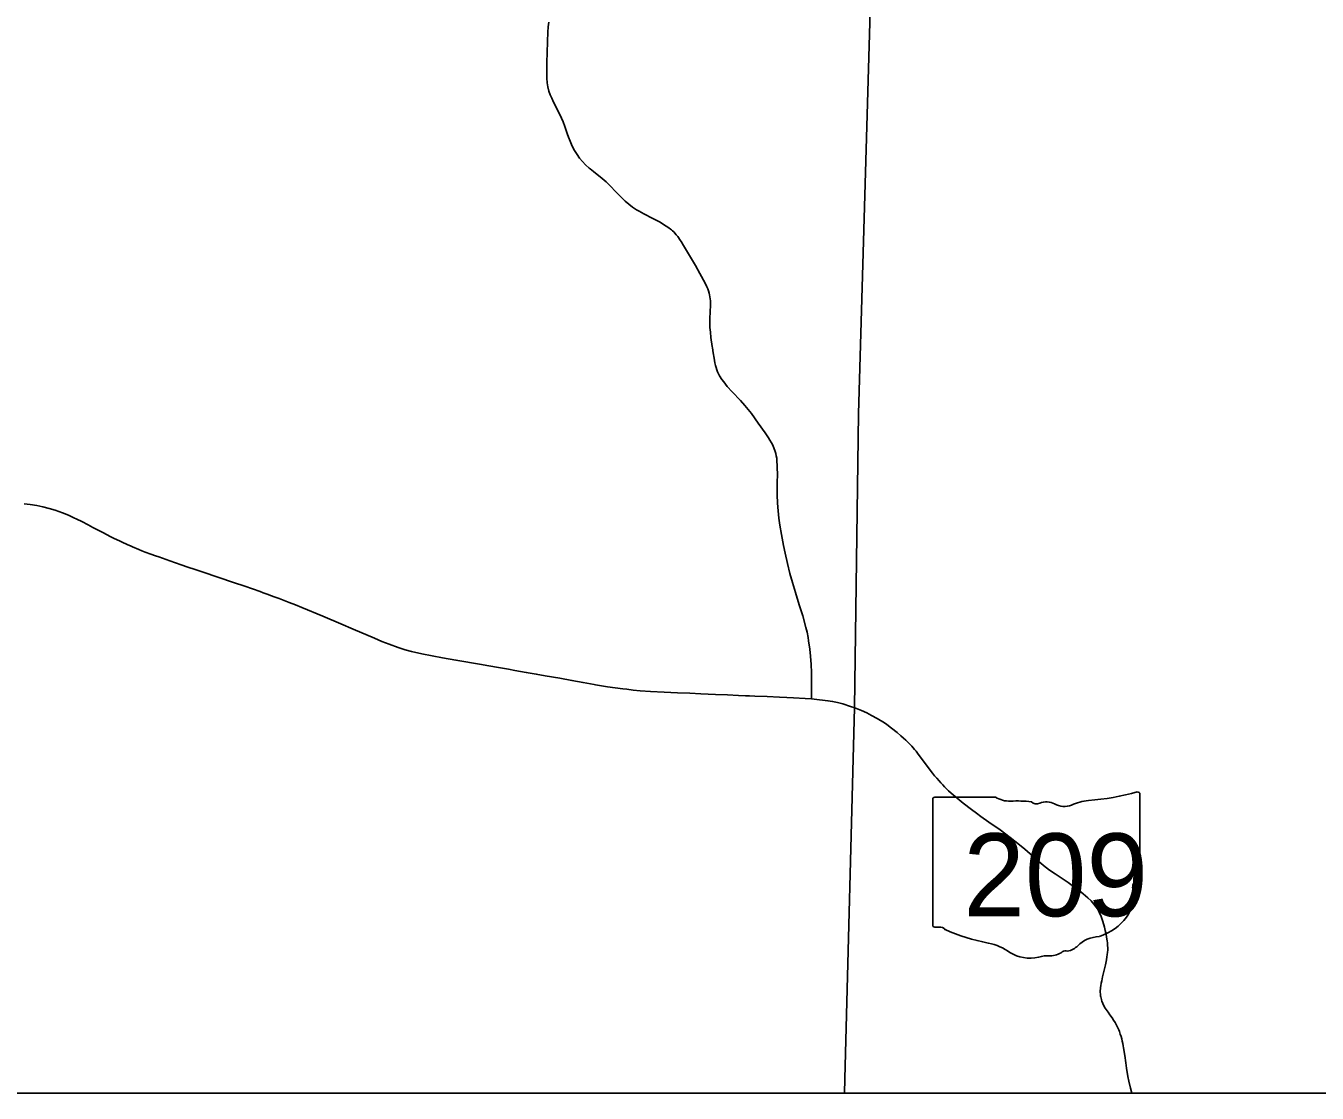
# Model space of a CAD drawing. Extents: x -12.1 to 34, y 0 to 22.
# Drawn here: x -10.219 to -8.292, y 10.977 to 12.57 of the extents above; entities that cross this region are included whole.
import ezdxf

# ---------------------------------------------------------------- set-up
doc = ezdxf.new("R2010")
doc.units = 0
for name, color, linetype in [('GM_X_State_Route', 7, 'Continuous'), ('GM_X_State_Shield', 7, 'Continuous'), ('GM_X_Township', 7, 'Continuous'), ('SH_Text', 7, 'Continuous')]:
    doc.layers.add(name, color=color, linetype=linetype)

msp = doc.modelspace()

# ---------------------------------------------------------------- linework, layer by layer
at = {"layer": 'GM_X_State_Route'}
for points in [[(-9.0469, 11.5656), (-9.0469, 11.569), (-9.0468, 11.5793), (-9.0467, 11.5896), (-9.0467, 11.5989), (-9.0468, 11.6051), (-9.0475, 11.6171), (-9.0483, 11.6292), (-9.0495, 11.6399), (-9.0512, 11.652), (-9.052, 11.6572), (-9.0536, 11.6651), (-9.0552, 11.6721), (-9.0599, 11.6893), (-9.0628, 11.6984), (-9.0653, 11.7059), (-9.0706, 11.7243), (-9.0754, 11.7394), (-9.079, 11.7528), (-9.0829, 11.7678), (-9.0864, 11.7829), (-9.0888, 11.7943), (-9.0918, 11.8109), (-9.0941, 11.8249), (-9.0956, 11.8353), (-9.0968, 11.8462), (-9.0975, 11.8574), (-9.098, 11.8699), (-9.098, 11.8897), (-9.0978, 11.8991), (-9.098, 11.9124), (-9.0985, 11.9218), (-9.0988, 11.9246), (-9.0994, 11.9284), (-9.1001, 11.9316), (-9.1006, 11.9333), (-9.1017, 11.9364), (-9.1041, 11.9424), (-9.1053, 11.9451), (-9.1067, 11.9478), (-9.109, 11.9517), (-9.1111, 11.9551), (-9.1162, 11.9627), (-9.1263, 11.9772), (-9.1365, 11.9912), (-9.1463, 12.0034), (-9.1528, 12.0107), (-9.1652, 12.0239), (-9.1725, 12.0317), (-9.1779, 12.0385), (-9.1808, 12.0422), (-9.184, 12.0475), (-9.187, 12.0537), (-9.1881, 12.0563), (-9.1893, 12.0598), (-9.1902, 12.0628), (-9.1911, 12.0669), (-9.1923, 12.074), (-9.1936, 12.0818), (-9.1947, 12.0892), (-9.195, 12.0915), (-9.1969, 12.105), (-9.1978, 12.1127), (-9.1985, 12.1197), (-9.1988, 12.1261), (-9.1986, 12.1336), (-9.1982, 12.1427), (-9.1977, 12.1535), (-9.1978, 12.1595), (-9.1981, 12.1626), (-9.1985, 12.1655), (-9.199, 12.1685), (-9.1996, 12.1711), (-9.2006, 12.1742), (-9.2018, 12.1774), (-9.2029, 12.1802), (-9.2054, 12.1856), (-9.2134, 12.2005), (-9.22, 12.2122), (-9.2287, 12.2269), (-9.2378, 12.2419), (-9.2414, 12.2478), (-9.2429, 12.25), (-9.2466, 12.2553), (-9.2487, 12.258), (-9.2524, 12.2625), (-9.2542, 12.264), (-9.2556, 12.2652), (-9.2571, 12.2665), (-9.2597, 12.2685), (-9.2636, 12.2711), (-9.2738, 12.2771), (-9.2835, 12.2824), (-9.297, 12.2893), (-9.3042, 12.2931), (-9.3081, 12.2954), (-9.3097, 12.2964), (-9.3139, 12.2993), (-9.3194, 12.3035), (-9.3251, 12.3084), (-9.3314, 12.3144), (-9.339, 12.3223), (-9.3474, 12.3312), (-9.3531, 12.3368), (-9.3592, 12.342), (-9.3722, 12.3524), (-9.3771, 12.3563), (-9.3787, 12.3576), (-9.3839, 12.3624), (-9.3888, 12.3672), (-9.3929, 12.3721), (-9.3968, 12.3779), (-9.4005, 12.384), (-9.4038, 12.3904), (-9.4072, 12.3979), (-9.4095, 12.4038), (-9.4115, 12.4091), (-9.4149, 12.4194), (-9.4175, 12.4264), (-9.4198, 12.4321), (-9.423, 12.4387), (-9.4319, 12.4557), (-9.4346, 12.4616), (-9.4369, 12.4669), (-9.4387, 12.4723), (-9.4403, 12.4786), (-9.4411, 12.4848), (-9.4416, 12.4916), (-9.4419, 12.5017), (-9.4419, 12.5156), (-9.4415, 12.5296), (-9.441, 12.5465), (-9.4405, 12.5605), (-9.4399, 12.5685), (-9.4391, 12.5754)], [(-10.2216, 11.8564), (-10.213, 11.8554), (-10.2031, 11.8539), (-10.1938, 11.8521), (-10.1843, 11.8497), (-10.1756, 11.8472), (-10.17, 11.8452), (-10.1648, 11.8433), (-10.1558, 11.8395), (-10.1476, 11.8358), (-10.1434, 11.8338), (-10.1356, 11.83), (-10.1263, 11.8251), (-10.1191, 11.8214), (-10.1145, 11.8189), (-10.1036, 11.8132), (-10.0933, 11.8079), (-10.0875, 11.8051), (-10.0796, 11.8012), (-10.0738, 11.7985), (-10.0701, 11.7969), (-10.0669, 11.7954), (-10.0632, 11.7938), (-10.06, 11.7924), (-10.0508, 11.7886), (-10.046, 11.7867), (-10.0411, 11.7847), (-10.0329, 11.7816), (-10.0258, 11.7791), (-10.0209, 11.7773), (-10.0042, 11.7714), (-9.9874, 11.7656), (-9.9778, 11.7621), (-9.9665, 11.7584), (-9.9545, 11.7546), (-9.9096, 11.7393), (-9.8926, 11.7336), (-9.8698, 11.7257), (-9.8651, 11.724), (-9.8594, 11.7219), (-9.8529, 11.7195), (-9.8485, 11.7179), (-9.8415, 11.7152), (-9.8387, 11.7142), (-9.8311, 11.7114), (-9.8262, 11.7095), (-9.817, 11.7059), (-9.8073, 11.702), (-9.7762, 11.6889), (-9.7494, 11.6777), (-9.7307, 11.6697), (-9.6992, 11.656), (-9.6879, 11.6512), (-9.677, 11.647), (-9.6638, 11.6423), (-9.6533, 11.6388), (-9.6437, 11.6362), (-9.6283, 11.6328), (-9.6129, 11.6296), (-9.5975, 11.6268), (-9.5774, 11.6234), (-9.5391, 11.6168), (-9.5316, 11.6156), (-9.511, 11.6119), (-9.499, 11.6097), (-9.4898, 11.608), (-9.4726, 11.6052), (-9.4577, 11.6026), (-9.4445, 11.6002), (-9.4226, 11.5964), (-9.4043, 11.5931), (-9.3877, 11.5899), (-9.3711, 11.587), (-9.3693, 11.5867), (-9.3515, 11.5838), (-9.34, 11.5821), (-9.3284, 11.5806), (-9.3226, 11.5799), (-9.3128, 11.5788), (-9.3024, 11.5777), (-9.2872, 11.5765), (-9.2669, 11.5754), (-9.2471, 11.5747), (-9.2285, 11.5741), (-9.2122, 11.5733), (-9.2012, 11.5728), (-9.1901, 11.5723), (-9.1721, 11.5715), (-9.1558, 11.5706), (-9.1453, 11.5701), (-9.1395, 11.5699), (-9.1315, 11.5697), (-9.1132, 11.569), (-9.0947, 11.5682), (-9.0837, 11.5678), (-9.0738, 11.5674), (-9.0564, 11.5664), (-9.0469, 11.5656), (-9.0431, 11.5653), (-9.0223, 11.5629), (-9.0154, 11.5617), (-9.0081, 11.5602), (-9.0002, 11.558), (-8.9886, 11.5544), (-8.9824, 11.5523)], [(-8.9824, 11.5523), (-8.9798, 11.5514), (-8.9723, 11.5483), (-8.9644, 11.5447), (-8.9572, 11.541), (-8.949, 11.5365), (-8.938, 11.5297), (-8.9347, 11.5273), (-8.9275, 11.5219), (-8.9192, 11.5155), (-8.9134, 11.5107), (-8.9094, 11.5071), (-8.9061, 11.5041), (-8.9026, 11.5007), (-8.8996, 11.4976), (-8.8972, 11.495), (-8.895, 11.4924), (-8.893, 11.4902), (-8.8909, 11.4874), (-8.8877, 11.4833), (-8.8738, 11.4648), (-8.8699, 11.4594), (-8.8665, 11.455), (-8.8631, 11.4508), (-8.8601, 11.4471), (-8.8566, 11.4432), (-8.8539, 11.4402), (-8.8511, 11.4372), (-8.8486, 11.4346), (-8.8457, 11.4318), (-8.8425, 11.4286), (-8.8385, 11.425), (-8.8296, 11.4174), (-8.8205, 11.41), (-8.808, 11.4005), (-8.8008, 11.3951), (-8.7941, 11.3901), (-8.7824, 11.3819), (-8.7656, 11.37), (-8.7504, 11.3589), (-8.7389, 11.35), (-8.7285, 11.3415), (-8.712, 11.3268), (-8.7005, 11.3169), (-8.6963, 11.3136), (-8.6916, 11.3102), (-8.6834, 11.3046), (-8.6742, 11.2985), (-8.6641, 11.2917), (-8.6522, 11.2833), (-8.648, 11.2802), (-8.6413, 11.2747), (-8.6382, 11.272), (-8.6347, 11.2689), (-8.6298, 11.2641), (-8.6278, 11.2619), (-8.6256, 11.2593), (-8.622, 11.2548), (-8.6203, 11.2522), (-8.6186, 11.2495), (-8.6174, 11.2473), (-8.6164, 11.2451), (-8.6152, 11.2423), (-8.614, 11.2394), (-8.6131, 11.2366), (-8.6121, 11.2333), (-8.6098, 11.2249), (-8.6086, 11.2198), (-8.6074, 11.2146), (-8.6066, 11.2101), (-8.6061, 11.2075), (-8.6056, 11.2043), (-8.6053, 11.202), (-8.6051, 11.1999), (-8.605, 11.1975), (-8.6049, 11.1942), (-8.6049, 11.1905), (-8.6051, 11.1877), (-8.6056, 11.1839), (-8.606, 11.1807), (-8.6068, 11.1761), (-8.6084, 11.1687), (-8.6112, 11.1569), (-8.6126, 11.1509), (-8.6138, 11.1451), (-8.6145, 11.1414), (-8.6152, 11.1375), (-8.6155, 11.1349), (-8.6157, 11.1328), (-8.6159, 11.1307), (-8.6159, 11.1288), (-8.6159, 11.1274), (-8.6158, 11.1257), (-8.6157, 11.1247), (-8.6155, 11.1235), (-8.6154, 11.1223), (-8.6152, 11.121), (-8.6148, 11.1191), (-8.6142, 11.117), (-8.6134, 11.1143), (-8.6128, 11.1126), (-8.6122, 11.1111), (-8.6115, 11.1094), (-8.6108, 11.1082), (-8.6101, 11.1068), (-8.6085, 11.1042), (-8.6044, 11.0982), (-8.6017, 11.0944), (-8.5984, 11.0896), (-8.596, 11.0861), (-8.5939, 11.0827), (-8.5921, 11.0797), (-8.5913, 11.078), (-8.5903, 11.076), (-8.5893, 11.074), (-8.5883, 11.0717), (-8.5873, 11.0691), (-8.5861, 11.0656), (-8.5849, 11.0621), (-8.5839, 11.0586), (-8.5831, 11.0551), (-8.5823, 11.0515), (-8.5817, 11.0482), (-8.5812, 11.0448), (-8.5795, 11.0335), (-8.578, 11.0227), (-8.5768, 11.0147), (-8.5747, 11.0021), (-8.5734, 10.9952), (-8.5711, 10.985), (-8.5691, 10.9773)]]:
    msp.add_lwpolyline(points, dxfattribs=at)
at = {"layer": 'GM_X_State_Shield'}
for p, q in [((-8.8658, 11.4157), (-8.8658, 11.2281)), ((-8.7723, 11.419), (-8.8628, 11.419)), ((-8.5568, 11.3255), (-8.5568, 11.4236)), ((-8.5569, 11.3255), (-8.5568, 11.3255))]:
    msp.add_line(p, q, dxfattribs=at)
for centre, major_axis, start_param, end_param in [((-8.8623, 11.4161), (0.00358, 0), 1.712693, 3.28349), ((-8.7507, 11.4407), (0.0347, 0), 4.042523, 4.731795), ((-8.7392, 11.3136), (0.1246, 0), 1.404758, 1.657858), ((-8.7109, 11.4171), (0.01, 0), 3.836095, 5.185415), ((-8.6962, 11.3954), (0.0208, 0), 0.950623, 2.079405), ((-8.6693, 11.4252), (0.0251, 0), 4.081561, 5.145723), ((-8.6251, 11.3617), (0.0659, 0), 1.699011, 2.107814), ((-8.6669, 11.6747), (0.3277, 0), 4.814394, 5.042369), ((-8.5603, 11.424), (0.00344, 0), 6.141152, 7.989035), ((-8.5576, 11.3183), (0.00532, 0), 1.883978, 3.671073), ((-8.5915, 11.3059), (0.032, 0), 5.934695, 6.695948), ((-8.5605, 11.3251), (0.00368, 0), 5.05454, 6.418171), ((-8.5445, 11.2844), (0.0232, 0), 2.387724, 3.262537), ((-8.6485, 11.2719), (0.082, 0), 5.101752, 6.440018), ((-8.8622, 11.2277), (0.00361, 0), 3.00124, 4.508301), ((-8.8617, 11.2469), (0.0276, 0), 4.665946, 4.897461), ((-8.8561, 11.2173), (0.00994, 0), 0.519207, 1.627899), ((-8.7306, 11.3859), (0.2366, 0), 4.195997, 4.488961), ((-8.8011, 11.1438), (0.074, 0), 0.823519, 1.323587), ((-8.6709, 11.2099), (0.0265, 0), 4.937069, 5.64225), ((-8.614, 11.1754), (0.0449, 0), 1.647645, 2.488434), ((-8.7211, 11.2164), (0.047, 0), 4.026481, 4.996735), ((-8.6939, 11.1515), (0.0386, 0), 1.495662, 1.94098), ((-8.6905, 11.2023), (0.025, 0), 4.691044, 5.507374), ((-8.6679, 11.1841), (0.00705, 0), 1.147584, 2.315152)]:
    msp.add_ellipse(centre, major_axis=major_axis, ratio=0.8, start_param=start_param, end_param=end_param, dxfattribs=at)
at = {"layer": 'GM_X_Township'}
msp.add_lwpolyline([(-8.9977, 10.9773), (-8.9971, 10.9988), (-8.9826, 11.5528), (-8.9766, 11.9907), (-8.9504, 12.9011), (-8.9441, 13.075), (-8.9332, 13.439), (-8.927, 13.7314), (-8.914, 14.2676)], dxfattribs=at)
at = {"layer": 'SH_Text'}
msp.add_lwpolyline([(-12.1463, 20.3063), (-4.4383, 20.3063), (-4.4383, 10.9773), (-12.1463, 10.9773)], close=True, dxfattribs=at)

# ---------------------------------------------------------------- texts
at = {"layer": 'GM_X_State_Shield'}
msp.add_text('209', height=0.1236, dxfattribs=at).set_placement((-8.8204, 11.2413))

doc.saveas('drawing.dxf')
